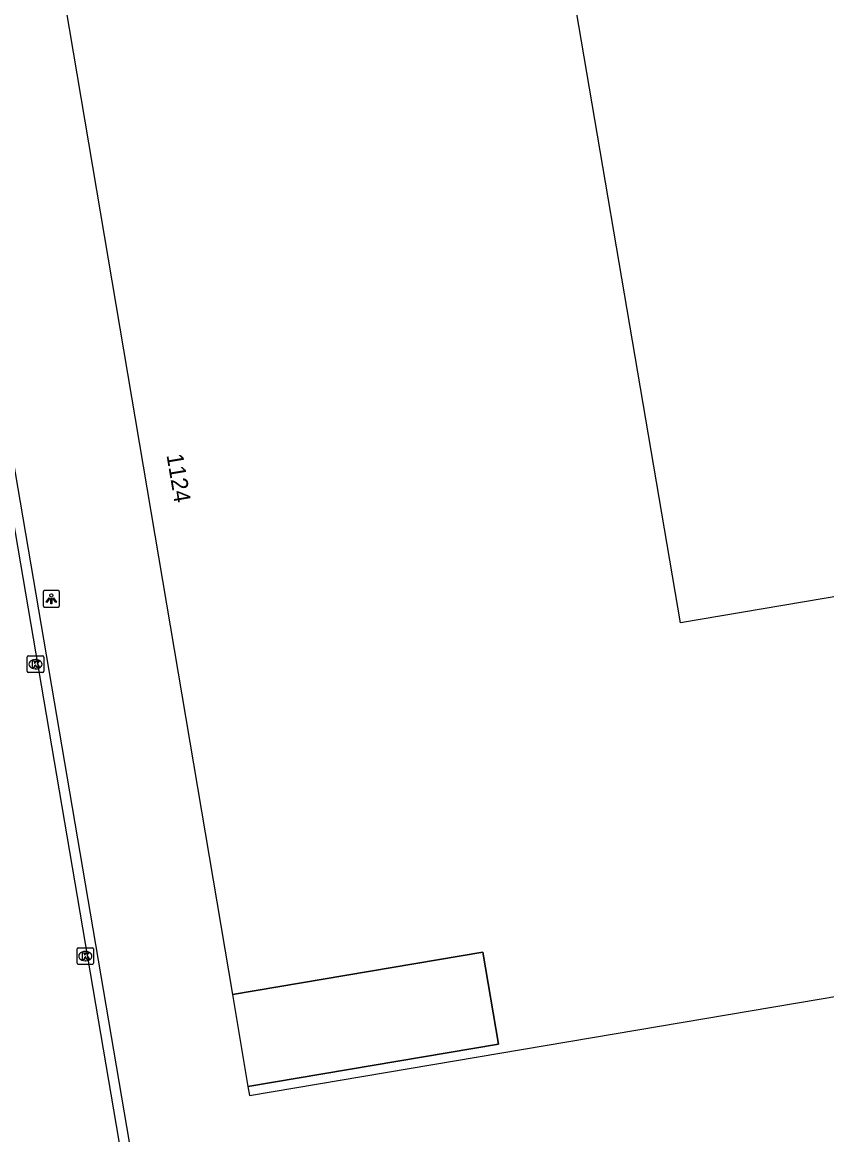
# Model space of a CAD drawing. Extents: x 154324 to 155743, y 382939 to 384183.
# Drawn here: x 154911.1 to 154959.7, y 383483.1 to 383550.2 of the extents above; entities that cross this region are included whole.
import ezdxf

# ---------------------------------------------------------------- set-up
doc = ezdxf.new("R2010")
doc.units = 0
for name, color, linetype in [('IMGEO_Kolk', 7, 'Continuous'), ('IMGEO_Lichtpunt', 7, 'Continuous'), ('IMGEO_Pand', 7, 'Continuous'), ('IMGEO_Pand_nummerreeks', 7, 'Continuous'), ('IMGEO_Pand_overbouw', 7, 'Continuous'), ('IMGEO_Rijbaan_lokaal_gesloten', 7, 'Continuous'), ('IMGEO_Rijbaan_lokaal_open', 7, 'Continuous')]:
    doc.layers.add(name, color=color, linetype=linetype)

msp = doc.modelspace()

# ---------------------------------------------------------------- linework, layer by layer
at = {"layer": 'IMGEO_Kolk'}
for p, q in [((154911.441, 383511.029), (154911.441, 383511.881)), ((154911.516, 383511.955), (154912.368, 383511.955)), ((154912.442, 383511.881), (154912.442, 383511.029)), ((154911.952, 383511.175), (154911.927, 383511.175)), ((154911.929, 383511.735), (154911.954, 383511.735)), ((154912.368, 383510.955), (154911.516, 383510.955)), ((154914.523, 383494.351), (154915.375, 383494.351)), ((154914.448, 383493.425), (154914.448, 383494.277)), ((154914.936, 383494.131), (154914.961, 383494.131)), ((154915.449, 383494.277), (154915.449, 383493.425)), ((154915.375, 383493.351), (154914.523, 383493.351)), ((154914.959, 383493.571), (154914.934, 383493.571))]:
    msp.add_line(p, q, dxfattribs=at)
for points in [[(154911.441, 383511.029), (154911.441, 383511.881)], [(154911.516, 383511.955), (154912.368, 383511.955)], [(154912.442, 383511.881), (154912.442, 383511.029)], [(154911.762, 383511.655), (154911.885, 383511.655), (154911.885, 383511.504), (154912.015, 383511.655), (154912.179, 383511.655), (154912.033, 383511.504), (154912.186, 383511.255), (154912.034, 383511.255), (154911.949, 383511.419), (154911.885, 383511.352), (154911.885, 383511.255), (154911.762, 383511.255), (154911.762, 383511.655)], [(154912.368, 383510.955), (154911.516, 383510.955)], [(154914.523, 383494.351), (154915.375, 383494.351)], [(154914.448, 383493.425), (154914.448, 383494.277)], [(154914.769, 383494.051), (154914.892, 383494.051), (154914.892, 383493.9), (154915.022, 383494.051), (154915.186, 383494.051), (154915.04, 383493.9), (154915.193, 383493.651), (154915.041, 383493.651), (154914.956, 383493.815), (154914.892, 383493.748), (154914.892, 383493.651), (154914.769, 383493.651), (154914.769, 383494.051)], [(154915.449, 383494.277), (154915.449, 383493.425)], [(154915.375, 383493.351), (154914.523, 383493.351)]]:
    msp.add_lwpolyline(points, dxfattribs=at)
for centre, start, end in [((154911.518, 383511.879), 91.55205, 178.44795), ((154911.518, 383511.879), 91.55205, 178.44795), ((154912.366, 383511.879), 1.55205, 88.44795), ((154912.366, 383511.879), 1.55205, 88.44795), ((154911.518, 383511.031), 181.55205, 268.44795), ((154911.518, 383511.031), 181.55205, 268.44795), ((154912.366, 383511.031), 271.55205, 358.44795), ((154912.366, 383511.031), 271.55205, 358.44795), ((154914.525, 383494.275), 91.55205, 178.44795), ((154914.525, 383494.275), 91.55205, 178.44795), ((154915.373, 383494.275), 1.55205, 88.44795), ((154915.373, 383494.275), 1.55205, 88.44795), ((154914.525, 383493.427), 181.55205, 268.44795), ((154914.525, 383493.427), 181.55205, 268.44795), ((154915.373, 383493.427), 271.55205, 358.44795), ((154915.373, 383493.427), 271.55205, 358.44795)]:
    msp.add_arc(centre, 0.0765, start, end, dxfattribs=at)
for centre, major_axis, ratio, start_param, end_param in [((154911.928, 383511.455), (-0.387, 0.002), 0.722429, 4.712389, 7.853982), ((154911.953, 383511.455), (-0.39, 0.002), 0.717154, 1.570796, 4.712389), ((154914.935, 383493.851), (-0.387, 0.002), 0.722429, 4.712389, 7.853982), ((154914.96, 383493.851), (-0.39, 0.002), 0.717154, 1.570796, 4.712389)]:
    msp.add_ellipse(centre, major_axis=major_axis, ratio=ratio, start_param=start_param, end_param=end_param, dxfattribs=at)
at = {"layer": 'IMGEO_Lichtpunt'}
for p, q in [((154913.3, 383515.897), (154912.492, 383515.897)), ((154913.3, 383515.897), (154912.492, 383515.897)), ((154912.398, 383515.802), (154912.398, 383514.995)), ((154912.398, 383515.802), (154912.398, 383514.995)), ((154913.394, 383514.995), (154913.394, 383515.802)), ((154913.394, 383514.995), (154913.394, 383515.802)), ((154912.492, 383514.901), (154913.3, 383514.901)), ((154912.492, 383514.901), (154913.3, 383514.901))]:
    msp.add_line(p, q, dxfattribs=at)
for points in [[(154912.772, 383515.466), (154912.811, 383515.438), (154912.623, 383515.176), (154912.585, 383515.203), (154912.772, 383515.466)], [(154912.874, 383515.418), (154912.921, 383515.418), (154912.921, 383515.096), (154912.874, 383515.096), (154912.874, 383515.418)], [(154912.984, 383515.438), (154913.022, 383515.465), (154913.209, 383515.203), (154913.17, 383515.175), (154912.984, 383515.438)]]:
    msp.add_lwpolyline(points, dxfattribs=at)
msp.add_circle((154912.897, 383515.6), 0.0994, dxfattribs=at)
for centre, start, end in [((154912.492, 383515.802), 90, 180), ((154912.492, 383515.802), 90, 180), ((154913.3, 383515.802), 0, 90), ((154913.3, 383515.802), 0, 90), ((154912.492, 383514.995), 180, 270), ((154912.492, 383514.995), 180, 270), ((154913.3, 383514.995), 270, 0), ((154913.3, 383514.995), 270, 360)]:
    msp.add_arc(centre, 0.0946, start, end, dxfattribs=at)
at = {"layer": 'IMGEO_Pand'}
msp.add_lwpolyline([(154942.463, 383563.229), (154912.559, 383558.136), (154923.822, 383491.524), (154938.938, 383494.079), (154939.875, 383488.538), (154924.759, 383485.982), (154924.851, 383485.44), (154964.694, 383492.169), (154960.716, 383515.618), (154950.858, 383513.939), (154942.463, 383563.229)], dxfattribs=at)
at = {"layer": 'IMGEO_Pand_overbouw'}
msp.add_lwpolyline([(154924.759, 383485.982), (154939.875, 383488.538), (154938.938, 383494.079), (154923.822, 383491.524)], close=True, dxfattribs=at)
at = {"layer": 'IMGEO_Rijbaan_lokaal_gesloten'}
msp.add_lwpolyline([(154859.21, 383821.776), (154860.592, 383813.666), (154872.994, 383740.868), (154875.261, 383727.607), (154875.734, 383724.688), (154937.891, 383359.922)], dxfattribs=at)
at = {"layer": 'IMGEO_Rijbaan_lokaal_open'}
msp.add_lwpolyline([(154936.699, 383370.542), (154936.688, 383370.604), (154886.005, 383668.098)], dxfattribs=at)

# ---------------------------------------------------------------- texts
at = {"layer": 'IMGEO_Pand_nummerreeks'}
msp.add_text('1124', height=1, rotation=279.59683, dxfattribs=at).set_placement((154919.84, 383524.07))

doc.saveas('drawing.dxf')
